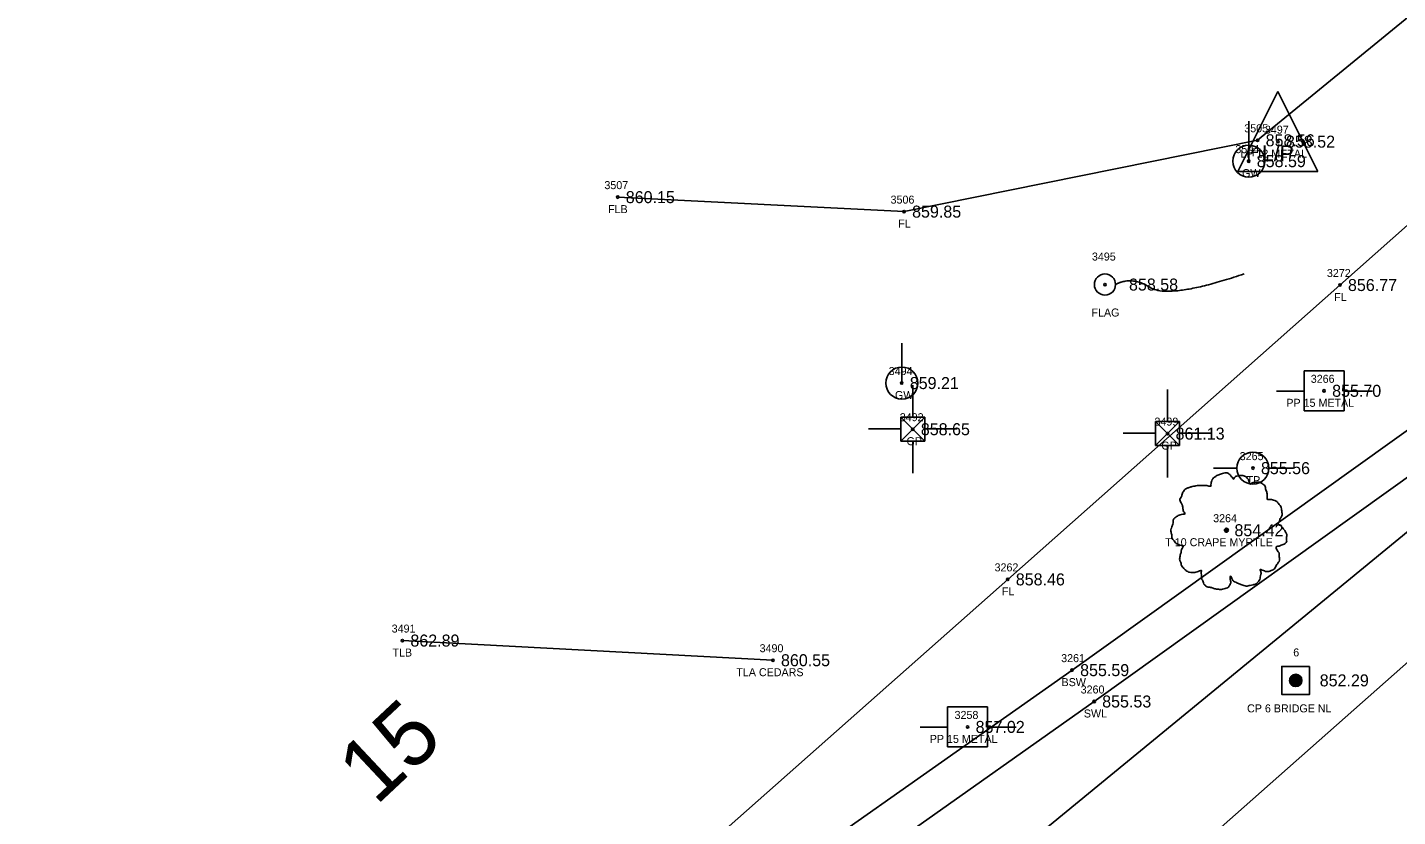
# Model space of a CAD drawing. Extents: x 1622501 to 1626664, y 1117816 to 1121579.
# Drawn here: x 1623866.8 to 1624038.1, y 1119331.4 to 1119430.1 of the extents above; entities that cross this region are included whole.
import ezdxf

# ---------------------------------------------------------------- set-up
doc = ezdxf.new("R2010")
doc.units = 0
for name, color, linetype in [('RD_EX_BldgApp_txCode', 7, 'Continuous'), ('RD_EX_Conc', 7, 'Continuous'), ('RD_EX_Conc_txCode', 7, 'Continuous'), ('RD_EX_DR_Pipe', 7, 'Continuous'), ('RD_EX_Fence_Other', 7, 'Continuous'), ('RD_EX_Fence_Other_txCode', 7, 'Continuous'), ('RD_EX_Road', 7, 'Continuous'), ('RD_EX_SU_Telecom', 7, 'Continuous'), ('RD_EX_TX_BldgApp_ELEV', 7, 'Continuous'), ('RD_EX_TX_Conc_ELEV', 7, 'Continuous'), ('RD_EX_TX_Fence_Other_ELEV', 7, 'Continuous'), ('RD_EX_TX_UT_ELEV', 7, 'Continuous'), ('RD_EX_TX_VEG_ELEV', 7, 'Continuous'), ('RD_EX_UT', 7, 'Continuous'), ('RD_EX_UT_txCode', 7, 'Continuous'), ('RD_EX_VEG', 7, 'Continuous'), ('RD_EX_VEG_txCode', 7, 'Continuous'), ('RD_HC_Survey', 7, 'Continuous'), ('RD_HC_Survey_ELEV', 7, 'Continuous'), ('RD_HC_Survey_txCode', 7, 'Continuous'), ('RD_HC_TX_Sta50', 7, 'Continuous'), ('RD_SMD_Locator', 7, 'Continuous')]:
    doc.layers.add(name, color=color, linetype=linetype)

msp = doc.modelspace()

# ---------------------------------------------------------------- linework, layer by layer
at = {"layer": 'RD_EX_Conc'}
for points in [[(1623883.58, 1119262.31), (1623914.11, 1119291.01), (1623949.14, 1119315.67), (1623997.41, 1119349.7), (1624041.95, 1119381.59), (1624076.33, 1119409.19), (1624117.51, 1119442.93), (1624154.84, 1119473.11), (1624194.15, 1119507.57), (1624227.99, 1119543.89), (1624253.61, 1119575.88), (1624290.62, 1119611.11), (1624311.93, 1119631.19), (1624320.3, 1119640.91)], [(1623887.3, 1119259.13), (1623917.26, 1119287.49), (1623952.1, 1119311.76), (1624000.17, 1119345.78), (1624044.86, 1119377.79), (1624079.21, 1119405.17), (1624120.3, 1119438.84), (1624157.17, 1119468.81), (1624198.23, 1119502.55), (1624231.93, 1119540.84), (1624256.76, 1119572.31), (1624294.22, 1119607.5), (1624315.43, 1119627.07), (1624326.01, 1119634.84)]]:
    msp.add_lwpolyline(points, dxfattribs=at)
at = {"layer": 'RD_EX_DR_Pipe'}
msp.add_lwpolyline([(1623859.42, 1119207.44), (1623928.36, 1119275.93), (1624053.59, 1119378.71), (1624148.05, 1119455.71), (1624257.33, 1119553.63), (1624257.33, 1119553.63), (1624370.57, 1119657.84)], dxfattribs=at)
at = {"layer": 'RD_EX_Fence_Other'}
for points in [[(1623864.47, 1119305.23), (1623867.28, 1119298.71), (1623872.01, 1119286.87), (1623881.85, 1119265.91), (1623912.38, 1119292.89), (1623945.47, 1119322.13), (1623989.37, 1119361.05), (1624030.89, 1119397.86), (1624061.41, 1119424.93), (1624104.3, 1119463.41), (1624135.03, 1119498.68), (1624164.28, 1119538.95), (1624168.7, 1119569.99)], [(1624086.45, 1119481.7), (1624090.79, 1119473.41), (1624020.6, 1119415.96), (1623976.41, 1119407.04), (1623940.62, 1119408.85)]]:
    msp.add_lwpolyline(points, dxfattribs=at)
at = {"layer": 'RD_EX_Road'}
msp.add_lwpolyline([(1623871.53, 1119282.43), (1623877.35, 1119269.36), (1623882.94, 1119261.68), (1623889.32, 1119256.29), (1623900.77, 1119250.58), (1623911.74, 1119248.84), (1623922.61, 1119250.1), (1623930.44, 1119253.06), (1623938.73, 1119260.81), (1623940.66, 1119261.07), (1623977.45, 1119294.81), (1624012.8, 1119327.2), (1624055.34, 1119364.81), (1624091.92, 1119394.37), (1624132.97, 1119426.42), (1624171.16, 1119456.67), (1624210.91, 1119487.9), (1624248.43, 1119517.93), (1624271.21, 1119536.86), (1624326.19, 1119588.45), (1624377.27, 1119636.65)], dxfattribs=at)
at = {"layer": 'RD_EX_SU_Telecom'}
msp.add_circle((1624001.52, 1119397.92), 1.32, dxfattribs=at)
msp.add_open_spline([(1624002.84, 1119397.92), (1624004.85, 1119399.02), (1624009.53, 1119396.07), (1624018.9, 1119399.25)], degree=2, dxfattribs=at)
at = {"layer": 'RD_EX_UT'}
for p, q in [((1624018.14, 1119412.06), (1624023.14, 1119422.06)), ((1624023.14, 1119422.06), (1624028.14, 1119412.06)), ((1624019.49, 1119413.35), (1624019.49, 1119418.35)), ((1624018.14, 1119412.06), (1624028.14, 1119412.06)), ((1623976.12, 1119385.6), (1623976.12, 1119390.6)), ((1624031.4, 1119387.14), (1624026.4, 1119387.14)), ((1624026.4, 1119387.14), (1624026.4, 1119382.14)), ((1624031.4, 1119382.14), (1624031.4, 1119387.14)), ((1623977.5, 1119381.33), (1623977.5, 1119385.33)), ((1624009.34, 1119380.78), (1624009.34, 1119384.78)), ((1624022.97, 1119384.58), (1624026.44, 1119384.58)), ((1624031.33, 1119384.58), (1624034.97, 1119384.58)), ((1624026.4, 1119382.14), (1624031.4, 1119382.14)), ((1623979, 1119381.33), (1623976, 1119378.33)), ((1623976, 1119381.33), (1623979, 1119378.33)), ((1623979, 1119381.33), (1623976, 1119381.33)), ((1623976, 1119381.33), (1623976, 1119378.33)), ((1623979, 1119378.33), (1623979, 1119381.33)), ((1624010.84, 1119380.78), (1624007.84, 1119377.78)), ((1624007.84, 1119380.78), (1624010.84, 1119377.78)), ((1624010.84, 1119380.78), (1624007.84, 1119380.78)), ((1624007.84, 1119380.78), (1624007.84, 1119377.78)), ((1624010.84, 1119377.78), (1624010.84, 1119380.78)), ((1623975.98, 1119379.87), (1623971.98, 1119379.87)), ((1623979.01, 1119379.89), (1623983.03, 1119379.89)), ((1624007.81, 1119379.33), (1624003.81, 1119379.33)), ((1624010.85, 1119379.35), (1624014.87, 1119379.35)), ((1623976, 1119378.33), (1623979, 1119378.33)), ((1623977.5, 1119378.33), (1623977.5, 1119374.33)), ((1624007.84, 1119377.78), (1624010.84, 1119377.78)), ((1624009.34, 1119377.78), (1624009.34, 1119373.78)), ((1624015.08, 1119374.97), (1624018.01, 1119374.97)), ((1624022.01, 1119374.97), (1624025.08, 1119374.97)), ((1623986.84, 1119345.11), (1623981.84, 1119345.11)), ((1623981.84, 1119345.11), (1623981.84, 1119340.11)), ((1623986.84, 1119340.11), (1623986.84, 1119345.11)), ((1623978.41, 1119342.55), (1623981.88, 1119342.55)), ((1623986.77, 1119342.55), (1623990.41, 1119342.55)), ((1623981.84, 1119340.11), (1623986.84, 1119340.11))]:
    msp.add_line(p, q, dxfattribs=at)
for centre in [(1624019.49, 1119413.35), (1623976.12, 1119385.6), (1624020.01, 1119374.96)]:
    msp.add_circle(centre, 2, dxfattribs=at)
at = {"layer": 'RD_EX_VEG'}
msp.add_line((1623960.02, 1119350.94), (1623913.7, 1119353.4), dxfattribs=at)
for centre, radius in [((1624016.7, 1119367.2), 0.25), ((1624016.68, 1119367.18), 0.0001)]:
    msp.add_circle(centre, radius, dxfattribs=at)
for points in [[(1624016.83, 1119374.37), (1624016.53, 1119374.39), (1624016.2, 1119374.29), (1624015.95, 1119374.19), (1624015.73, 1119374.12), (1624015.51, 1119374.02), (1624015.21, 1119373.84), (1624014.98, 1119373.64), (1624014.86, 1119373.39), (1624014.81, 1119373.17), (1624014.76, 1119372.89), (1624014.76, 1119372.72), (1624014.63, 1119372.69), (1624014.48, 1119372.72), (1624014.23, 1119372.79), (1624013.98, 1119372.79), (1624013.73, 1119372.79), (1624013.38, 1119372.77), (1624013.03, 1119372.77), (1624012.76, 1119372.72), (1624012.43, 1119372.67), (1624012.06, 1119372.54), (1624011.71, 1119372.42), (1624011.41, 1119372.17), (1624011.16, 1119371.69), (1624011.03, 1119371.34), (1624010.88, 1119371.09), (1624011.03, 1119370.64), (1624011.21, 1119370.29), (1624011.23, 1119370.09), (1624011.31, 1119369.67), (1624011.41, 1119369.44), (1624011.53, 1119369.24), (1624011.46, 1119369.22), (1624011.08, 1119369.17), (1624010.78, 1119369.07), (1624010.36, 1119368.84), (1624010.13, 1119368.62), (1624010.03, 1119368.3), (1624010.01, 1119367.95), (1624009.91, 1119367.75), (1624009.83, 1119367.47), (1624009.81, 1119367.4), (1624009.76, 1119367.07), (1624009.86, 1119366.62), (1624009.88, 1119366.27), (1624010.01, 1119366.05), (1624010.16, 1119365.87), (1624010.33, 1119365.62), (1624010.73, 1119365.4), (1624011.06, 1119365.3), (1624011.26, 1119365.27), (1624011.08, 1119364.77), (1624011.03, 1119364.42), (1624010.91, 1119364.02), (1624010.91, 1119363.95), (1624010.86, 1119363.47), (1624011.01, 1119363.15), (1624011.08, 1119362.77), (1624011.26, 1119362.55), (1624011.53, 1119362.25), (1624011.86, 1119362.02), (1624012.36, 1119361.9), (1624012.76, 1119361.92), (1624013.33, 1119362.1), (1624013.58, 1119362.17), (1624013.56, 1119362), (1624013.58, 1119361.62), (1624013.58, 1119361.2), (1624013.73, 1119360.87), (1624013.83, 1119360.6), (1624013.98, 1119360.35), (1624014.31, 1119360.12), (1624014.71, 1119360.05), (1624015.13, 1119359.9), (1624015.58, 1119359.82), (1624016.08, 1119359.8), (1624016.68, 1119359.95), (1624016.95, 1119360.07), (1624017.05, 1119360.25), (1624017.25, 1119360.62), (1624017.2, 1119360.85), (1624017.23, 1119361.45), (1624017.33, 1119361.27), (1624017.5, 1119360.92), (1624018, 1119360.62), (1624018.4, 1119360.45), (1624018.88, 1119360.3), (1624019.18, 1119360.22), (1624019.65, 1119360.3), (1624020.03, 1119360.37), (1624020.4, 1119360.5), (1624020.7, 1119360.77), (1624020.88, 1119361.05), (1624020.93, 1119361.32), (1624021, 1119361.7), (1624021.05, 1119361.87)], [(1624021.05, 1119361.87), (1624020.98, 1119362.05), (1624020.93, 1119362.3), (1624021, 1119362.27), (1624021.18, 1119362.22), (1624021.45, 1119362.1), (1624021.68, 1119362.02), (1624022, 1119362.05), (1624022.28, 1119362.15), (1624022.73, 1119362.42), (1624023, 1119362.9), (1624023.28, 1119363.3), (1624023.35, 1119363.62), (1624023.3, 1119363.85), (1624023.28, 1119364.35), (1624023.08, 1119364.6), (1624023.03, 1119364.72), (1624022.93, 1119365.12), (1624023, 1119365.17), (1624023.28, 1119365.22), (1624023.65, 1119365.35), (1624023.93, 1119365.47), (1624024.15, 1119365.65), (1624024.23, 1119365.87), (1624024.2, 1119366.27), (1624024.25, 1119366.67), (1624024.18, 1119366.82), (1624024.08, 1119366.97), (1624024, 1119367.17), (1624023.85, 1119367.32), (1624023.75, 1119367.47), (1624023.65, 1119367.57), (1624023.53, 1119367.72), (1624023.35, 1119367.85), (1624023.2, 1119367.9), (1624023.15, 1119368.05), (1624023.3, 1119368.25), (1624023.35, 1119368.35), (1624023.38, 1119368.57), (1624023.6, 1119368.92), (1624023.65, 1119369.32), (1624023.6, 1119369.74), (1624023.55, 1119370.02), (1624023.4, 1119370.29), (1624023.2, 1119370.54), (1624023.08, 1119370.72), (1624022.9, 1119370.84), (1624022.58, 1119370.97), (1624022.33, 1119371.02), (1624021.98, 1119371.02), (1624021.78, 1119371.07), (1624021.8, 1119371.12), (1624021.8, 1119371.27), (1624021.8, 1119371.54), (1624021.73, 1119371.99), (1624021.58, 1119372.49), (1624021.58, 1119372.52), (1624021.48, 1119372.77), (1624021.25, 1119372.97), (1624021.08, 1119373.07), (1624020.88, 1119373.19), (1624020.63, 1119373.22), (1624020.33, 1119373.22), (1624020.05, 1119373.17), (1624019.85, 1119373.07), (1624019.68, 1119372.94), (1624019.6, 1119373.09), (1624019.5, 1119373.39), (1624019.45, 1119373.54), (1624019.3, 1119373.72), (1624019.08, 1119373.92), (1624018.63, 1119374.04), (1624018, 1119373.97), (1624017.7, 1119373.77), (1624017.55, 1119373.59), (1624017.5, 1119373.72), (1624017.3, 1119373.92), (1624017.2, 1119374.09), (1624017.03, 1119374.22), (1624016.88, 1119374.32), (1624016.78, 1119374.37)]]:
    msp.add_spline(points, degree=3, dxfattribs=at)
at = {"layer": 'RD_HC_Survey'}
for p, q in [((1624024.61, 1119348.24), (1624024.61, 1119348.6)), ((1624024.63, 1119348.16), (1624024.63, 1119348.68)), ((1624024.66, 1119348.09), (1624024.66, 1119348.74)), ((1624024.68, 1119348.05), (1624024.68, 1119348.79)), ((1624024.71, 1119348), (1624024.71, 1119348.83)), ((1624024.73, 1119347.97), (1624024.73, 1119348.87)), ((1624024.76, 1119347.94), (1624024.76, 1119348.9)), ((1624024.78, 1119347.91), (1624024.78, 1119348.93)), ((1624024.8, 1119347.88), (1624024.8, 1119348.95)), ((1624024.83, 1119347.86), (1624024.83, 1119348.98)), ((1624024.85, 1119347.83), (1624024.85, 1119349)), ((1624024.88, 1119347.81), (1624024.88, 1119349.02)), ((1624024.9, 1119347.79), (1624024.9, 1119349.04)), ((1624024.93, 1119347.78), (1624024.93, 1119349.06)), ((1624024.95, 1119347.76), (1624024.95, 1119349.07)), ((1624024.98, 1119347.75), (1624024.98, 1119349.09)), ((1624025, 1119347.73), (1624025, 1119349.1)), ((1624025.03, 1119347.72), (1624025.03, 1119349.11)), ((1624025.05, 1119347.71), (1624025.05, 1119349.12)), ((1624025.08, 1119347.7), (1624025.08, 1119349.13)), ((1624025.1, 1119347.69), (1624025.1, 1119349.14)), ((1624025.13, 1119347.68), (1624025.13, 1119349.15)), ((1624025.15, 1119347.68), (1624025.15, 1119349.16)), ((1624025.18, 1119347.67), (1624025.18, 1119349.17)), ((1624025.2, 1119347.66), (1624025.2, 1119349.17)), ((1624025.23, 1119347.66), (1624025.23, 1119349.18)), ((1624025.25, 1119347.65), (1624025.25, 1119349.18)), ((1624025.27, 1119347.65), (1624025.27, 1119349.18)), ((1624025.3, 1119347.65), (1624025.3, 1119349.18)), ((1624025.32, 1119347.65), (1624025.32, 1119349.19)), ((1624025.35, 1119347.65), (1624025.35, 1119349.19)), ((1624025.37, 1119347.65), (1624025.37, 1119349.19)), ((1624025.4, 1119347.65), (1624025.4, 1119349.19)), ((1624025.42, 1119347.65), (1624025.42, 1119349.18)), ((1624025.45, 1119347.65), (1624025.45, 1119349.18)), ((1624025.47, 1119347.66), (1624025.47, 1119349.18)), ((1624025.5, 1119347.66), (1624025.5, 1119349.17)), ((1624025.52, 1119347.67), (1624025.52, 1119349.17)), ((1624025.55, 1119347.67), (1624025.55, 1119349.16)), ((1624025.57, 1119347.68), (1624025.57, 1119349.16)), ((1624025.6, 1119347.69), (1624025.6, 1119349.15)), ((1624025.62, 1119347.7), (1624025.62, 1119349.14)), ((1624025.65, 1119347.7), (1624025.65, 1119349.13)), ((1624025.67, 1119347.72), (1624025.67, 1119349.12)), ((1624025.7, 1119347.73), (1624025.7, 1119349.11)), ((1624025.72, 1119347.74), (1624025.72, 1119349.09)), ((1624025.75, 1119347.75), (1624025.75, 1119349.08)), ((1624025.77, 1119347.77), (1624025.77, 1119349.07)), ((1624025.79, 1119347.79), (1624025.79, 1119349.05)), ((1624025.82, 1119347.8), (1624025.82, 1119349.03)), ((1624025.84, 1119347.82), (1624025.84, 1119349.01)), ((1624025.87, 1119347.84), (1624025.87, 1119348.99)), ((1624025.89, 1119347.87), (1624025.89, 1119348.97)), ((1624025.92, 1119347.89), (1624025.92, 1119348.94)), ((1624025.94, 1119347.92), (1624025.94, 1119348.91)), ((1624025.97, 1119347.95), (1624025.97, 1119348.88)), ((1624025.99, 1119347.99), (1624025.99, 1119348.85)), ((1624026.02, 1119348.03), (1624026.02, 1119348.81)), ((1624026.04, 1119348.07), (1624026.04, 1119348.76)), ((1624026.07, 1119348.12), (1624026.07, 1119348.71)), ((1624026.09, 1119348.19), (1624026.09, 1119348.64)), ((1624026.12, 1119348.31), (1624026.12, 1119348.53))]:
    msp.add_line(p, q, dxfattribs=at)
msp.add_lwpolyline([(1624027.1, 1119350.17), (1624023.61, 1119350.17), (1624023.61, 1119346.67), (1624027.1, 1119346.67)], close=True, dxfattribs=at)
msp.add_circle((1624025.36, 1119348.42), 0.769, dxfattribs=at)
at = {"layer": 'RD_SMD_Locator'}
for centre in [(1624020.6, 1119415.96), (1624023.14, 1119415.79), (1624019.49, 1119413.35), (1623940.62, 1119408.85), (1623976.41, 1119407.04), (1624001.52, 1119397.92), (1624030.89, 1119397.86), (1623976.12, 1119385.6), (1624028.91, 1119384.63), (1623977.5, 1119379.83), (1624009.34, 1119379.28), (1624020.01, 1119374.96), (1624016.7, 1119367.2), (1623989.37, 1119361.05), (1623913.7, 1119353.4), (1623960.02, 1119350.94), (1623997.41, 1119349.7), (1624025.36, 1119348.42), (1624000.17, 1119345.78), (1623984.35, 1119342.6)]:
    msp.add_circle(centre, 0.15, dxfattribs=at)

# ---------------------------------------------------------------- texts
at = {"layer": 'RD_EX_BldgApp_txCode'}
for s, p in [('3495', (1623999.89, 1119400.92)), ('FLAG', (1623999.83, 1119393.92))]:
    msp.add_text(s, height=1, dxfattribs=at).set_placement(p)
at = {"layer": 'RD_EX_Conc_txCode'}
for s, p in [('3261', (1623996.04, 1119350.7)), ('BSW', (1623996.09, 1119347.7)), ('3260', (1623998.48, 1119346.78)), ('SWL', (1623998.88, 1119343.78))]:
    msp.add_text(s, height=1, dxfattribs=at).set_placement(p)
at = {"layer": 'RD_EX_Fence_Other_txCode'}
for s, p in [('3505', (1624018.93, 1119416.96)), ('FL', (1624019.87, 1119413.96)), ('3507', (1623938.95, 1119409.85)), ('FLB', (1623939.41, 1119406.85)), ('3506', (1623974.72, 1119408.04)), ('FL', (1623975.68, 1119405.04)), ('3272', (1624029.26, 1119398.86)), ('FL', (1624030.16, 1119395.86)), ('3262', (1623987.72, 1119362.05)), ('FL', (1623988.64, 1119359.05))]:
    msp.add_text(s, height=1, dxfattribs=at).set_placement(p)
at = {"layer": 'RD_EX_TX_BldgApp_ELEV'}
msp.add_text('858.58', height=1.5, dxfattribs=at).set_placement((1624004.52, 1119397.17))
at = {"layer": 'RD_EX_TX_Conc_ELEV'}
for s, p in [('855.59', (1623998.41, 1119348.95)), ('855.53', (1624001.17, 1119345.03))]:
    msp.add_text(s, height=1.5, dxfattribs=at).set_placement(p)
at = {"layer": 'RD_EX_TX_Fence_Other_ELEV'}
for s, p in [('858.56', (1624021.6, 1119415.21)), ('860.15', (1623941.62, 1119408.1)), ('859.85', (1623977.41, 1119406.29)), ('856.77', (1624031.89, 1119397.11)), ('858.46', (1623990.37, 1119360.3))]:
    msp.add_text(s, height=1.5, dxfattribs=at).set_placement(p)
at = {"layer": 'RD_EX_TX_UT_ELEV'}
for s, p in [('858.52', (1624024.14, 1119415.04)), ('858.59', (1624020.49, 1119412.6)), ('859.21', (1623977.12, 1119384.85)), ('858.65', (1623978.5, 1119379.08)), ('861.13', (1624010.34, 1119378.53)), ('855.56', (1624021.01, 1119374.21))]:
    msp.add_text(s, height=1.5, dxfattribs=at).set_placement(p)
at = {"layer": 'RD_EX_TX_VEG_ELEV'}
for s, p in [('854.42', (1624017.7, 1119366.45)), ('862.89', (1623914.7, 1119352.65)), ('860.55', (1623961.02, 1119350.19))]:
    msp.add_text(s, height=1.5, dxfattribs=at).set_placement(p)
at = {"layer": 'RD_EX_UT'}
msp.add_text('L/P', height=2, dxfattribs=at).set_placement((1624021.13, 1119413.34))
at = {"layer": 'RD_EX_UT_txCode'}
for s, p in [('3497', (1624021.51, 1119416.79)), ('3504', (1624017.82, 1119414.35)), ('LP 12 METAL', (1624018.44, 1119413.79)), ('GW', (1624018.65, 1119411.35)), ('3494', (1623974.49, 1119386.6)), ('3266', (1624027.24, 1119385.63)), ('GW', (1623975.27, 1119383.6)), ('PP 15 METAL', (1624024.19, 1119382.63)), ('3492', (1623975.87, 1119380.83)), ('3499', (1624007.71, 1119380.28)), ('GP', (1623976.72, 1119377.83)), ('GP', (1624008.56, 1119377.28)), ('3265', (1624018.36, 1119375.96)), ('TP', (1624019.22, 1119372.96)), ('3258', (1623982.72, 1119343.6)), ('PP 15 METAL', (1623979.62, 1119340.6))]:
    msp.add_text(s, height=1, dxfattribs=at).set_placement(p)
at = {"layer": 'RD_EX_VEG_txCode'}
for s, p in [('3264', (1624015.04, 1119368.2)), ('T 10 CRAPE MYRTLE', (1624009.05, 1119365.2)), ('3491', (1623912.36, 1119354.4)), ('3490', (1623958.35, 1119351.94)), ('TLB', (1623912.46, 1119351.4)), ('TLA CEDARS', (1623955.44, 1119348.94))]:
    msp.add_text(s, height=1, dxfattribs=at).set_placement(p)
at = {"layer": 'RD_HC_Survey_ELEV'}
for s, p in [('855.70', (1624029.91, 1119383.88)), ('852.29', (1624028.36, 1119347.67)), ('857.02', (1623985.35, 1119341.85))]:
    msp.add_text(s, height=1.5, dxfattribs=at).set_placement(p)
at = {"layer": 'RD_HC_Survey_txCode'}
for s, p in [('6', (1624025.05, 1119351.42)), ('CP 6 BRIDGE NL', (1624019.28, 1119344.42))]:
    msp.add_text(s, height=1, dxfattribs=at).set_placement(p)
at = {"layer": 'RD_HC_TX_Sta50'}
msp.add_text('15', height=8, rotation=43.1627, dxfattribs=at).set_placement((1623910.39, 1119332.66))

doc.saveas('drawing.dxf')
